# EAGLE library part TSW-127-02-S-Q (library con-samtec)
THROUGH-HOLE .025" SQ POST HEADER Source: Samtec TSW.pdf
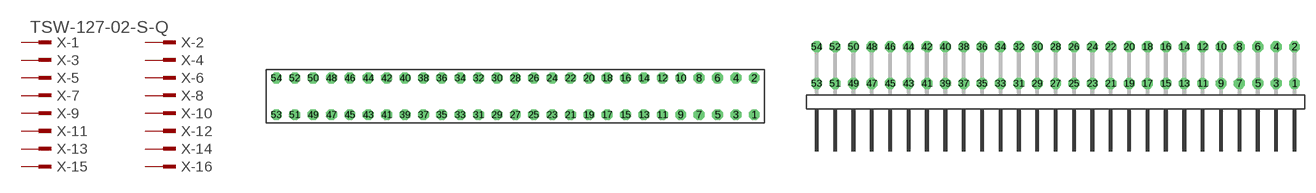
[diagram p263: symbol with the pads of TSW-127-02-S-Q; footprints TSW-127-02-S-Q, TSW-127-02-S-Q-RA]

Designator prefix X; gates -1=MPINV -2=MPIN -3=MPIN -4=MPIN -5=MPIN -6=MPIN -7=MPIN -8=MPIN -9=MPIN -10=MPIN -11=MPIN -12=MPIN -13=MPIN -14=MPIN -15=MPIN -16=MPIN -17=MPIN -18=MPIN -19=MPIN -20=MPIN -21=MPIN -22=MPIN -23=MPIN -24=MPIN -25=MPIN -26=MPIN -27=MPIN -28=MPIN -29=MPIN -30=MPIN -31=MPIN -32=MPIN -33=MPIN -34=MPIN -35=MPIN -36=MPIN -37=MPIN -38=MPIN -39=MPIN -40=MPIN -41=MPIN -42=MPIN -43=MPIN -44=MPIN -45=MPIN -46=MPIN -47=MPIN -48=MPIN -49=MPIN -50=MPIN -51=MPIN -52=MPIN -53=MPIN -54=MPIN

## TSW-127-02-S-Q (OC_FARNELL: unknown; OC_NEWARK: unknown)  [TSW-127-02-S-Q]
1  -1:1  pas
2  -2:1  pas
3  -3:1  pas
4  -4:1  pas
5  -5:1  pas
6  -6:1  pas
7  -7:1  pas
8  -8:1  pas
9  -9:1  pas
10  -10:1  pas
11  -11:1  pas
12  -12:1  pas
13  -13:1  pas
14  -14:1  pas
15  -15:1  pas
16  -16:1  pas
17  -17:1  pas
18  -18:1  pas
19  -19:1  pas
20  -20:1  pas
21  -21:1  pas
22  -22:1  pas
23  -23:1  pas
24  -24:1  pas
25  -25:1  pas
26  -26:1  pas
27  -27:1  pas
28  -28:1  pas
29  -29:1  pas
30  -30:1  pas
31  -31:1  pas
32  -32:1  pas
33  -33:1  pas
34  -34:1  pas
35  -35:1  pas
36  -36:1  pas
37  -37:1  pas
38  -38:1  pas
39  -39:1  pas
40  -40:1  pas
41  -41:1  pas
42  -42:1  pas
43  -43:1  pas
44  -44:1  pas
45  -45:1  pas
46  -46:1  pas
47  -47:1  pas
48  -48:1  pas
49  -49:1  pas
50  -50:1  pas
51  -51:1  pas
52  -52:1  pas
53  -53:1  pas
54  -54:1  pas

## TSW-127-02-S-Q-RA (OC_FARNELL: unknown; OC_NEWARK: unknown)  [TSW-127-02-S-Q-RA]
Pads as for TSW-127-02-S-Q

## Footprint TSW-127-02-S-Q (pad centres in mm)
THROUGH-HOLE .025" SQ POST HEADER Source: Samtec TSW.pdf
drill 1 pad 1.5 octagon: 1 33.02,-2.54; 2 33.02,2.54; 3 30.48,-2.54; 4 30.48,2.54; 5 27.94,-2.54; 6 27.94,2.54; 7 25.4,-2.54; 8 25.4,2.54; 9 22.86,-2.54; 10 22.86,2.54; 11 20.32,-2.54; 12 20.32,2.54; 13 17.78,-2.54; 14 17.78,2.54; 15 15.24,-2.54; 16 15.24,2.54; 17 12.7,-2.54; 18 12.7,2.54; 19 10.16,-2.54; 20 10.16,2.54; 21 7.62,-2.54; 22 7.62,2.54; 23 5.08,-2.54; 24 5.08,2.54; 25 2.54,-2.54; 26 2.54,2.54; 27 0,-2.54; 28 0,2.54; 29 -2.54,-2.54; 30 -2.54,2.54; 31 -5.08,-2.54; 32 -5.08,2.54; 33 -7.62,-2.54; 34 -7.62,2.54; 35 -10.16,-2.54; 36 -10.16,2.54; 37 -12.7,-2.54; 38 -12.7,2.54; 39 -15.24,-2.54; 40 -15.24,2.54; 41 -17.78,-2.54; 42 -17.78,2.54; 43 -20.32,-2.54; 44 -20.32,2.54; 45 -22.86,-2.54; 46 -22.86,2.54; 47 -25.4,-2.54; 48 -25.4,2.54; 49 -27.94,-2.54; 50 -27.94,2.54; 51 -30.48,-2.54; 52 -30.48,2.54; 53 -33.02,-2.54; 54 -33.02,2.54

## Footprint TSW-127-02-S-Q-RA (pad centres in mm)
THROUGH-HOLE .025" SQ POST HEADER Source: Samtec TSW.pdf
drill 1 pad 1.5 octagon: 1 33.02,1.524; 2 33.02,6.604; 3 30.48,1.524; 4 30.48,6.604; 5 27.94,1.524; 6 27.94,6.604; 7 25.4,1.524; 8 25.4,6.604; 9 22.86,1.524; 10 22.86,6.604; 11 20.32,1.524; 12 20.32,6.604; 13 17.78,1.524; 14 17.78,6.604; 15 15.24,1.524; 16 15.24,6.604; 17 12.7,1.524; 18 12.7,6.604; 19 10.16,1.524; 20 10.16,6.604; 21 7.62,1.524; 22 7.62,6.604; 23 5.08,1.524; 24 5.08,6.604; 25 2.54,1.524; 26 2.54,6.604; 27 0,1.524; 28 0,6.604; 29 -2.54,1.524; 30 -2.54,6.604; 31 -5.08,1.524; 32 -5.08,6.604; 33 -7.62,1.524; 34 -7.62,6.604; 35 -10.16,1.524; 36 -10.16,6.604; 37 -12.7,1.524; 38 -12.7,6.604; 39 -15.24,1.524; 40 -15.24,6.604; 41 -17.78,1.524; 42 -17.78,6.604; 43 -20.32,1.524; 44 -20.32,6.604; 45 -22.86,1.524; 46 -22.86,6.604; 47 -25.4,1.524; 48 -25.4,6.604; 49 -27.94,1.524; 50 -27.94,6.604; 51 -30.48,1.524; 52 -30.48,6.604; 53 -33.02,1.524; 54 -33.02,6.604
